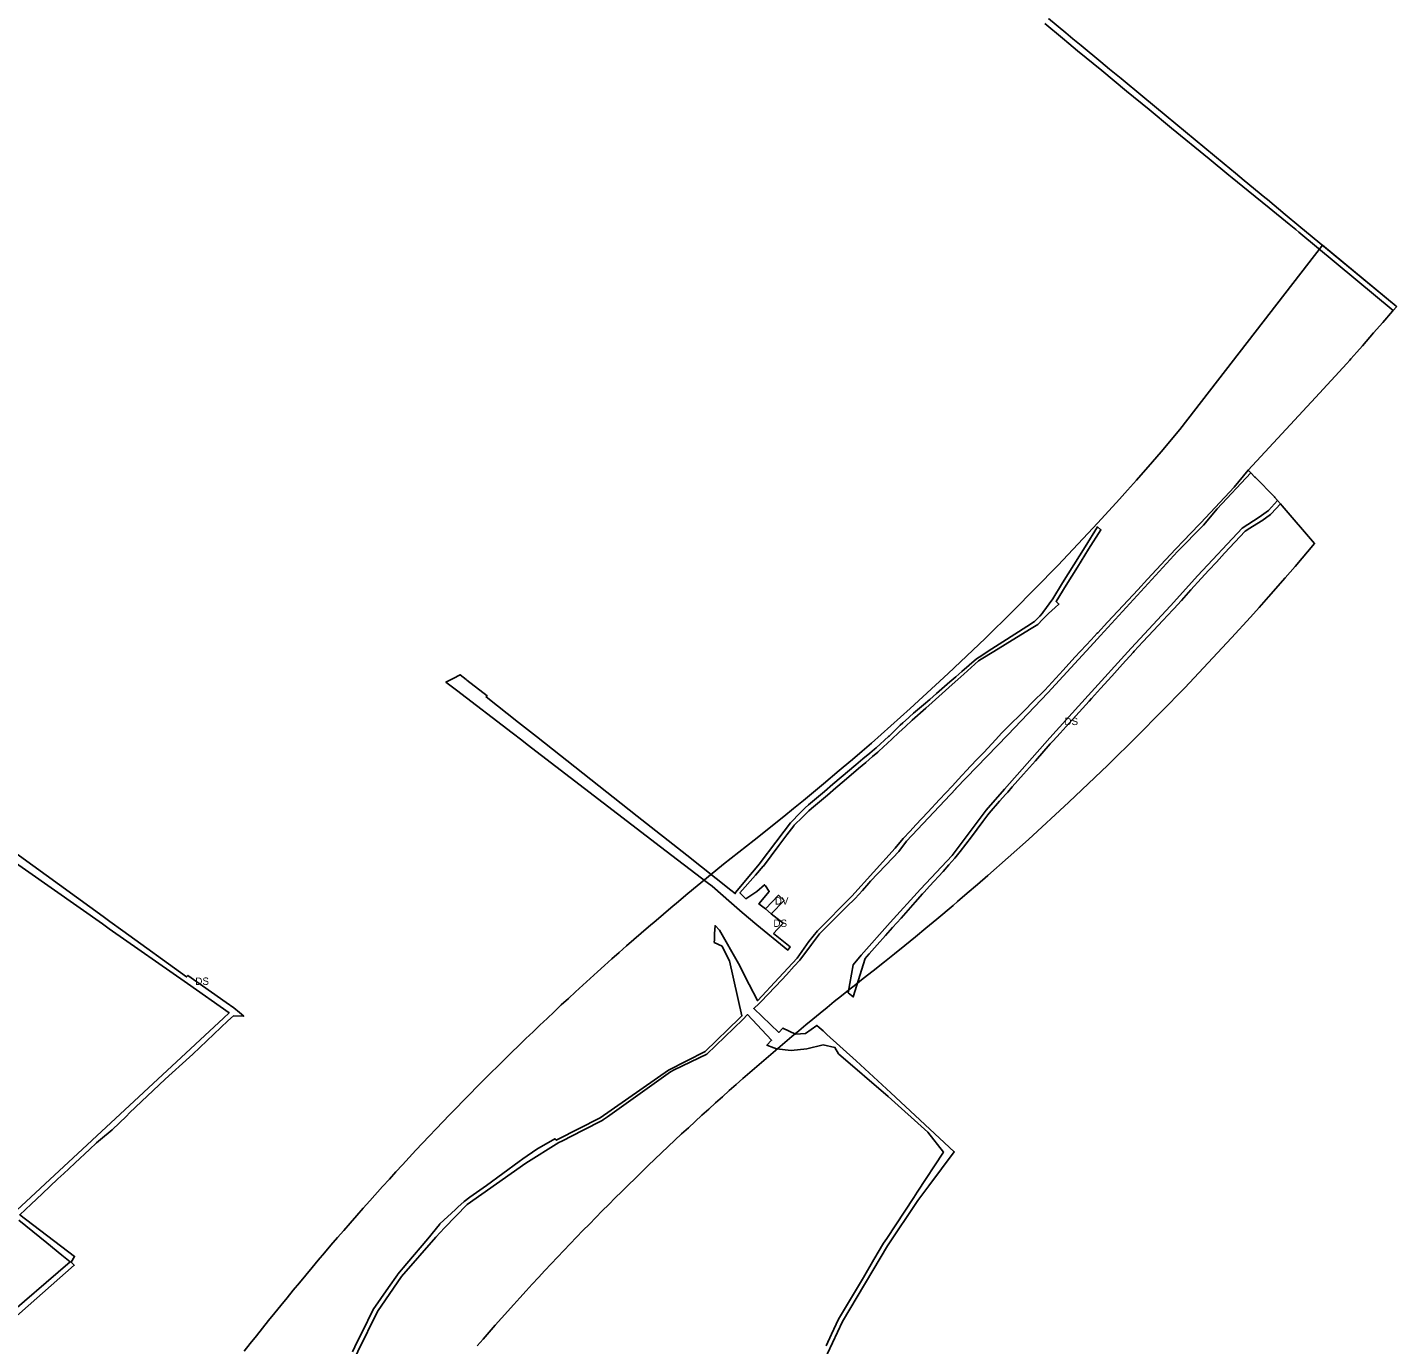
# Model space of a CAD drawing. Extents: x -537034 to -534353, y -1176562 to -1173176.
# Drawn here: x -535284 to -534353, y -1175321 to -1174424 of the extents above; entities that cross this region are included whole.
import ezdxf

# ---------------------------------------------------------------- set-up
doc = ezdxf.new("R2010")
doc.units = 0
for name, color, linetype in [('90320013', 7, 'Continuous'), ('90350013', 7, 'Continuous'), ('90350033', 7, 'Continuous')]:
    doc.layers.add(name, color=color, linetype=linetype)

msp = doc.modelspace()

# ---------------------------------------------------------------- linework, layer by layer
at = {"layer": '90320013'}
for points in [[(-534589.93, -1174418.12), (-534578.03, -1174428.04), (-534573.25, -1174432.03), (-534567.68, -1174436.64), (-534554.19, -1174447.79), (-534548.35, -1174452.63), (-534540.48, -1174459.14), (-534525.72, -1174471.35), (-534509.87, -1174484.46), (-534483.54, -1174506.24), (-534470.29, -1174517.2), (-534462.6, -1174523.56), (-534456.81, -1174528.36), (-534442.82, -1174539.95), (-534440.99, -1174541.47), (-534428.86, -1174551.52), (-534419.54, -1174559.24), (-534353.44, -1174614.02), (-534353.08, -1174614.32), (-534355.38, -1174616.95), (-534419.61, -1174563.52), (-534421.64, -1174561.87), (-534426.11, -1174558.23), (-534439.81, -1174547.07), (-534454.04, -1174535.48), (-534464.98, -1174526.57), (-534467.19, -1174524.75), (-534480.58, -1174513.75), (-534506.13, -1174492.75), (-534521.39, -1174480.21), (-534536.75, -1174467.59), (-534553.67, -1174453.68), (-534570.13, -1174440.15), (-534576.11, -1174435.24), (-534580.43, -1174431.59), (-534592.27, -1174421.58)], [(-535063.39, -1175325.47), (-535060.09, -1175318.76), (-535056.8, -1175312.07), (-535049.22, -1175296.61), (-535038.82, -1175281.72), (-535032.81, -1175273.11), (-535032.45, -1175272.59), (-535026.36, -1175265.47), (-535012.03, -1175248.73), (-535004.26, -1175238.84), (-535003.94, -1175238.43), (-534993.31, -1175228.6), (-534991.63, -1175227.05), (-534987.36, -1175223.18), (-534983.42, -1175220.32), (-534972.25, -1175212.22), (-534949.86, -1175195.98), (-534947.44, -1175194.22), (-534937.89, -1175187.69), (-534925.65, -1175180.5), (-534924.68, -1175181.38), (-534923.98, -1175180.93), (-534894.94, -1175166.32), (-534848.38, -1175133.87), (-534823.52, -1175121.25), (-534800, -1175098.5), (-534798.45, -1175096.97), (-534806.93, -1175059.47), (-534810.08, -1175053.22), (-534811.97, -1175049.46), (-534817.23, -1175046.88), (-534817.15, -1175045), (-534816.98, -1175041.13), (-534816.74, -1175035.44), (-534813.71, -1175038.69), (-534800.74, -1175061.15), (-534793.42, -1175075.61), (-534787.86, -1175086.44), (-534787.72, -1175086.34), (-534773.26, -1175070.93), (-534773.24, -1175070.91), (-534760.89, -1175057.67), (-534760.8, -1175057.54), (-534752.93, -1175046.38), (-534747.13, -1175039.14), (-534723.62, -1175015.5), (-534694.19, -1174982.86), (-534688.65, -1174976.17), (-534684.1, -1174971.29), (-534680.11, -1174967.01), (-534676.03, -1174962.63), (-534672.06, -1174958.37), (-534663.93, -1174949.64), (-534659.79, -1174945.2), (-534655.44, -1174940.54), (-534655.2, -1174940.28), (-534651.23, -1174936.04), (-534642.84, -1174927.08), (-534638.3, -1174922.23), (-534633.94, -1174917.57), (-534625.7, -1174908.76), (-534621.84, -1174904.63), (-534620.16, -1174902.84), (-534618.12, -1174900.81), (-534606.77, -1174889.47), (-534599.87, -1174882.57), (-534593.35, -1174876.06), (-534592.47, -1174875.18), (-534579.89, -1174861.57), (-534571.86, -1174852.88), (-534564.27, -1174844.66), (-534560.85, -1174840.96), (-534556.76, -1174836.54), (-534556.43, -1174836.18), (-534549.73, -1174828.99), (-534542.79, -1174821.53), (-534535.79, -1174814.01), (-534529.2, -1174806.94), (-534522.47, -1174799.71), (-534516.46, -1174793.26), (-534510.2, -1174786.54), (-534503.37, -1174779.2), (-534498.14, -1174773.7), (-534493.01, -1174768.32), (-534487.23, -1174762.24), (-534486.32, -1174761.29), (-534463.51, -1174737.19), (-534454.07, -1174725.53), (-534452.32, -1174727.32), (-534475.1, -1174751.76), (-534484.54, -1174763.09), (-534502.13, -1174780.9), (-534554.55, -1174837.98), (-534559.14, -1174842.98), (-534590.44, -1174877.09), (-534617.54, -1174905.69), (-534652.92, -1174942.24), (-534653.01, -1174942.33), (-534686.41, -1174978.09), (-534691.73, -1174984.99), (-534695.79, -1174989.31), (-534700.74, -1174994.57), (-534710.89, -1175005.34), (-534712.15, -1175006.68), (-534716.5, -1175011.48), (-534721.5, -1175016.99), (-534727.33, -1175022.8), (-534733.34, -1175028.8), (-534745.39, -1175040.83), (-534745.62, -1175041.13), (-534751.09, -1175048.36), (-534759.09, -1175058.95), (-534762.82, -1175063.03), (-534768.18, -1175068.9), (-534771.39, -1175072.42), (-534785.44, -1175087.07), (-534786.8, -1175088.49), (-534790.32, -1175091.91), (-534790.4, -1175091.99), (-534773.31, -1175108.17), (-534770.56, -1175105.2), (-534761.9, -1175109.38), (-534755.11, -1175109), (-534747.48, -1175103.4), (-534745.98, -1175104.75), (-534743.28, -1175107.18), (-534740.58, -1175109.61), (-534720.8, -1175127.43), (-534697.1, -1175149.18), (-534653.97, -1175189.37), (-534671.31, -1175212.56), (-534678.69, -1175222.42), (-534699.3, -1175253.32), (-534730.05, -1175304.93), (-534747.12, -1175341.05)], [(-535310.83, -1174973.08), (-535242.13, -1175022.75), (-535233.05, -1175029.31), (-535228.44, -1175032.64), (-535219.53, -1175039.08), (-535176.19, -1175070.42), (-535175.34, -1175069.39), (-535149.3, -1175087.74), (-535144.09, -1175091.41), (-535140.17, -1175094.69), (-535137.28, -1175097.12), (-535144.39, -1175096.9), (-535148.04, -1175100.34), (-535171.9, -1175122.87), (-535174.24, -1175125.08), (-535190.77, -1175139.87), (-535215.05, -1175162.99), (-535217.18, -1175165.05), (-535226.88, -1175174.43), (-535234.65, -1175180.94), (-535237.5, -1175183.32), (-535242.22, -1175187.74), (-535252.09, -1175196.99), (-535256.36, -1175200.99), (-535259.81, -1175204.23), (-535263.71, -1175207.89), (-535274.41, -1175217.92), (-535281.94, -1175224.98), (-535289.65, -1175232.2), (-535252.39, -1175260.55), (-535254.7, -1175264.4), (-535252.65, -1175266.55), (-535299.55, -1175307.94)], [(-535294.94, -1175232.04), (-535151.14, -1175098.4), (-535147.24, -1175094.77), (-535175.51, -1175074.96), (-535228.85, -1175037.59), (-535233.44, -1175034.37), (-535301.06, -1174986.97)], [(-534741.19, -1175321.42), (-534737.42, -1175313.42), (-534734.3, -1175306.78), (-534732.7, -1175303.37), (-534730.67, -1175299.94), (-534723.88, -1175288.45), (-534715.83, -1175274.83), (-534708.7, -1175262.76), (-534702.15, -1175251.67), (-534699.91, -1175248.4), (-534681.52, -1175220.48), (-534679.16, -1175216.88), (-534661.36, -1175189.66), (-534671.99, -1175175.95), (-534698.96, -1175151.8), (-534732.83, -1175122.62), (-534735.14, -1175118.41), (-534743.23, -1175116.69), (-534754.23, -1175119.31), (-534764.86, -1175120.57), (-534774.86, -1175119.44), (-534776.64, -1175118.75), (-534781.42, -1175116.91), (-534778.21, -1175113.45), (-534778.22, -1175113.45), (-534794.55, -1175096.02), (-534797.92, -1175099.3), (-534822.38, -1175122.93), (-534844.45, -1175133.62), (-534847.04, -1175134.87), (-534889.89, -1175165.51), (-534892.59, -1175167.44), (-534893.48, -1175168.07), (-534906.46, -1175174.67), (-534921.01, -1175182.07), (-534922.88, -1175183.02), (-534945.43, -1175197.06), (-534985.25, -1175225.31), (-535000.77, -1175241.14), (-535006.62, -1175247.42), (-535030.1, -1175274.28), (-535046.44, -1175297.98), (-535073.18, -1175352.43)], [(-535302.84, -1175305.19), (-535255.37, -1175264.33), (-535261.08, -1175259.67), (-535271.33, -1175251.31), (-535290.22, -1175235.89)]]:
    msp.add_lwpolyline(points, dxfattribs=at)
for points in [[(-534726.06, -1175081.25), (-534722.76, -1175062.11), (-534717.3, -1175055.5), (-534697.52, -1175033.38), (-534676.86, -1175010.7), (-534655.43, -1174987.67), (-534632.39, -1174956.93), (-534619.84, -1174942.57), (-534589.01, -1174907.71), (-534562.86, -1174878.98), (-534533.72, -1174846.67), (-534506.9, -1174817.91), (-534488.33, -1174797.34), (-534458.12, -1174764.98), (-534446.52, -1174757.52), (-534440.14, -1174752.91), (-534434.05, -1174746.09), (-534432.09, -1174748.37), (-534438.37, -1174755.36), (-534438.8, -1174755.67), (-534444.75, -1174759.97), (-534445.17, -1174760.23), (-534452.95, -1174765.07), (-534456.21, -1174767.1), (-534470.07, -1174782.05), (-534475.68, -1174788.11), (-534480.75, -1174793.58), (-534486.14, -1174799.39), (-534492.97, -1174806.95), (-534499.52, -1174814.21), (-534504.67, -1174819.92), (-534505.32, -1174820.62), (-534512.17, -1174827.96), (-534518.45, -1174834.69), (-534525.62, -1174842.38), (-534531.53, -1174848.72), (-534532.32, -1174849.59), (-534539.53, -1174857.59), (-534546.87, -1174865.73), (-534554.5, -1174874.18), (-534560.64, -1174880.98), (-534562.26, -1174882.76), (-534575.89, -1174897.74), (-534581.98, -1174904.44), (-534586.79, -1174909.73), (-534588.66, -1174911.85), (-534598.76, -1174923.27), (-534602.87, -1174927.92), (-534606.8, -1174932.37), (-534614.56, -1174941.14), (-534617.59, -1174944.56), (-534618.91, -1174946.08), (-534623.14, -1174950.91), (-534630.19, -1174958.97), (-534631.12, -1174960.2), (-534634.53, -1174964.69), (-534638.47, -1174969.88), (-534642.34, -1174974.97), (-534649.98, -1174985.02), (-534653.5, -1174989.66), (-534657.59, -1174994.15), (-534661.59, -1174998.56), (-534670.85, -1175008.75), (-534674.52, -1175012.78), (-534675.58, -1175013.96), (-534680.57, -1175019.56), (-534690.19, -1175030.35), (-534695.91, -1175036.77), (-534700.74, -1175042.19), (-534706.46, -1175048.6), (-534711.9, -1175054.7), (-534713.41, -1175056.39), (-534714.69, -1175057.83), (-534722.75, -1175084.04), (-534725.07, -1175082.09)], [(-534782.29, -1175024), (-534778.49, -1175027.49), (-534770.39, -1175033.81), (-534774.24, -1175037.93), (-534776.91, -1175040.75), (-534765.58, -1175050.02), (-534767.31, -1175052.15), (-534788.2, -1175034.87), (-534798.18, -1175026.62), (-534805.63, -1175020.1), (-534818.78, -1175008.59), (-534821.98, -1175006.14), (-534853.75, -1174981.84), (-534944.54, -1174912.26), (-534948.24, -1174909.32), (-534954.69, -1174904.38), (-534992.69, -1174875.28), (-534999.77, -1174869.82), (-534994.52, -1174867.04), (-534990.63, -1174864.98), (-534990.18, -1174864.74), (-534985.93, -1174868.07), (-534985.56, -1174868.36), (-534971.8, -1174879.12), (-534972.43, -1174879.91), (-534950.35, -1174897.34), (-534938.24, -1174906.9), (-534869.76, -1174960.94), (-534836.01, -1174987.56), (-534805.96, -1175011.28), (-534802.96, -1175013.64), (-534802.78, -1175012.88), (-534791.25, -1174999.12), (-534786.4, -1174993.33), (-534785.92, -1174992.69), (-534775.34, -1174978.66), (-534769.74, -1174971.23), (-534765.49, -1174965.6), (-534764.81, -1174964.9), (-534759.21, -1174959.17), (-534755.41, -1174955.28), (-534753.14, -1174953.36), (-534742.3, -1174944.19), (-534736.54, -1174939.32), (-534730.87, -1174934.52), (-534721.01, -1174926.18), (-534716.11, -1174922.04), (-534711.49, -1174918.14), (-534708.32, -1174915.45), (-534707.2, -1174914.47), (-534698.64, -1174906.9), (-534698.23, -1174906.49), (-534693.48, -1174901.76), (-534690.89, -1174899.19), (-534688.97, -1174897.47), (-534685.1, -1174894.02), (-534684.36, -1174893.38), (-534681.63, -1174891.01), (-534674.99, -1174885.26), (-534670.72, -1174881.56), (-534666.1, -1174877.56), (-534656.99, -1174869.67), (-534652.89, -1174866.12), (-534648.87, -1174862.64), (-534638.95, -1174854.04), (-534636.95, -1174852.75), (-534628.44, -1174847.25), (-534620.87, -1174842.36), (-534604.65, -1174831.87), (-534599.49, -1174828.54), (-534595.88, -1174824.89), (-534594.13, -1174823.13), (-534593.65, -1174822.45), (-534587.03, -1174813.03), (-534580.26, -1174802.17), (-534572.63, -1174789.92), (-534565.02, -1174777.71), (-534556.56, -1174764.15), (-534554.28, -1174766.1), (-534562.58, -1174779.41), (-534570.19, -1174791.62), (-534577.84, -1174803.89), (-534584.75, -1174814.98), (-534582.77, -1174816.67), (-534585.4, -1174819.11), (-534589.81, -1174823.19), (-534591.85, -1174825.08), (-534593.92, -1174827.17), (-534597.21, -1174830.49), (-534602.88, -1174833.99), (-534619.38, -1174844.19), (-534627.07, -1174848.94), (-534635.7, -1174854.27), (-534637.43, -1174855.34), (-534647.49, -1174864.35), (-534651.46, -1174867.9), (-534655.51, -1174871.52), (-534664.5, -1174879.56), (-534669.06, -1174883.64), (-534673.31, -1174887.44), (-534682.55, -1174895.71), (-534682.82, -1174895.96), (-534687.06, -1174899.88), (-534691.61, -1174904.08), (-534696.53, -1174908.62), (-534705.36, -1174916.77), (-534706.04, -1174917.4), (-534709.63, -1174920.47), (-534714.23, -1174924.39), (-534719.08, -1174928.54), (-534728.92, -1174936.95), (-534734.55, -1174941.76), (-534740.27, -1174946.65), (-534751.08, -1174955.89), (-534752.89, -1174957.43), (-534757.18, -1174961.64), (-534762.89, -1174967.22), (-534763.21, -1174967.54), (-534767.78, -1174973.61), (-534773.36, -1174981.02), (-534783.84, -1174994.93), (-534784, -1174995.14), (-534789.27, -1175001.16), (-534799.77, -1175013.15), (-534795.76, -1175017.23), (-534788.3, -1175012.3), (-534782.97, -1175007.65), (-534782.3, -1175008.34), (-534779.83, -1175012.16), (-534786.84, -1175020.73)]]:
    msp.add_lwpolyline(points, close=True, dxfattribs=at)
at = {"layer": '90350013'}
msp.add_lwpolyline([(-534782.29, -1175024), (-534773.59, -1175014.79), (-534769.81, -1175018.3), (-534778.49, -1175027.49)], close=True, dxfattribs=at)
at = {"layer": '90350033'}
msp.add_lwpolyline([(-535136.94, -1175325.16), (-535132.84, -1175319.92), (-535128.73, -1175314.69), (-535124.59, -1175309.47), (-535120.44, -1175304.27), (-535116.27, -1175299.08), (-535112.08, -1175293.9), (-535107.88, -1175288.74), (-535103.66, -1175283.58), (-535099.42, -1175278.45), (-535095.16, -1175273.32), (-535090.89, -1175268.21), (-535086.6, -1175263.12), (-535082.42, -1175258.19), (-535077.98, -1175252.95), (-535073.49, -1175247.76), (-535069.26, -1175242.87), (-535064.89, -1175237.85), (-535060.49, -1175232.83), (-535056.09, -1175227.84), (-535051.6, -1175222.78), (-535042.82, -1175213), (-535038.28, -1175207.99), (-535033.79, -1175203.07), (-535029.28, -1175198.16), (-535024.76, -1175193.26), (-535020.22, -1175188.38), (-535015.66, -1175183.52), (-535011.09, -1175178.67), (-535006.5, -1175173.83), (-535001.9, -1175169.01), (-534997.28, -1175164.21), (-534992.65, -1175159.42), (-534988, -1175154.65), (-534983.33, -1175149.89), (-534978.65, -1175145.15), (-534973.95, -1175140.42), (-534969.24, -1175135.71), (-534964.51, -1175131.02), (-534959.77, -1175126.34), (-534955.02, -1175121.68), (-534950.39, -1175117.18), (-534945.47, -1175112.38), (-534940.5, -1175107.65), (-534935.84, -1175103.19), (-534931.01, -1175098.61), (-534926.16, -1175094.05), (-534921.3, -1175089.5), (-534916.43, -1175084.97), (-534911.54, -1175080.46), (-534906.64, -1175075.96), (-534901.72, -1175071.48), (-534896.79, -1175067.02), (-534891.85, -1175062.57), (-534886.89, -1175058.14), (-534881.92, -1175053.73), (-534876.93, -1175049.33), (-534871.93, -1175044.95), (-534866.92, -1175040.59), (-534861.89, -1175036.25), (-534856.85, -1175031.92), (-534851.8, -1175027.61), (-534846.74, -1175023.32), (-534841.66, -1175019.04), (-534836.56, -1175014.79), (-534831.46, -1175010.55), (-534826.34, -1175006.33), (-534821.21, -1175002.13), (-534816.07, -1174997.94), (-534810.91, -1174993.77), (-534805.75, -1174989.62), (-534800.57, -1174985.49), (-534795.38, -1174981.38), (-534790.18, -1174977.29), (-534783.54, -1174972.06), (-534776.41, -1174966.39), (-534769.98, -1174961.23), (-534763.24, -1174955.78), (-534756.51, -1174950.28), (-534749.82, -1174944.77), (-534742.88, -1174939), (-534732.18, -1174929.99), (-534729.52, -1174927.75), (-534723.23, -1174922.37), (-534716.63, -1174916.68), (-534710.36, -1174911.24), (-534684.02, -1174887.83), (-534658.03, -1174863.91), (-534632.98, -1174840.01), (-534614.26, -1174821.59), (-534583.65, -1174790.4), (-534559.44, -1174764.73), (-534553.86, -1174758.68), (-534541.6, -1174745.2), (-534536.13, -1174739.11), (-534530.09, -1174732.33), (-534519.24, -1174719.98), (-534513.25, -1174713.07), (-534500.44, -1174697.95), (-534403.55, -1174572.5), (-534353.44, -1174614.02), (-534353.08, -1174614.32), (-534355.38, -1174616.95), (-534355.78, -1174617.4), (-534362.47, -1174625.07), (-534368.7, -1174632.2), (-534376.27, -1174640.88), (-534380.19, -1174645.37), (-534384.14, -1174649.9), (-534384.9, -1174650.72), (-534387.03, -1174653.03), (-534408.37, -1174676.1), (-534454.07, -1174725.53), (-534452.32, -1174727.32), (-534449.49, -1174730.22), (-534449.18, -1174730.55), (-534436.26, -1174743.82), (-534435.92, -1174744.17), (-534434.05, -1174746.09), (-534432.09, -1174748.37), (-534430.84, -1174749.83), (-534408.87, -1174775.5), (-534422.13, -1174791.15), (-534428.84, -1174798.89), (-534440.2, -1174811.82), (-534446.66, -1174819.09), (-534452.58, -1174825.67), (-534465.38, -1174839.74), (-534471.68, -1174846.57), (-534497.16, -1174873.59), (-534529.34, -1174906.39), (-534549.48, -1174926.2), (-534575.97, -1174951.47), (-534603.52, -1174976.83), (-534631.15, -1175001.39), (-534638.12, -1175007.44), (-534645.11, -1175013.46), (-534651.79, -1175019.16), (-534654.77, -1175021.69), (-534665.88, -1175031.04), (-534673.31, -1175037.22), (-534680.41, -1175043.07), (-534687.55, -1175048.9), (-534694.69, -1175054.68), (-534701.53, -1175060.16), (-534709.07, -1175066.16), (-534715.94, -1175071.57), (-534721.01, -1175075.56), (-534725.89, -1175079.43), (-534730.76, -1175083.31), (-534735.62, -1175087.21), (-534740.48, -1175091.14), (-534745.32, -1175095.08), (-534750.14, -1175099.03), (-534754.95, -1175102.99), (-534759.75, -1175106.98), (-534764.54, -1175110.99), (-534769.32, -1175115.01), (-534774.08, -1175119.04), (-534778.83, -1175123.1), (-534783.57, -1175127.16), (-534788.3, -1175131.25), (-534793.02, -1175135.36), (-534797.72, -1175139.47), (-534802.41, -1175143.61), (-534807.08, -1175147.76), (-534811.75, -1175151.92), (-534816.4, -1175156.11), (-534821.04, -1175160.31), (-534825.66, -1175164.52), (-534830.28, -1175168.75), (-534834.87, -1175173), (-534839.45, -1175177.25), (-534844.02, -1175181.53), (-534848.58, -1175185.83), (-534853.13, -1175190.14), (-534857.66, -1175194.46), (-534862.19, -1175198.78), (-534866.67, -1175203.15), (-534871.16, -1175207.52), (-534875.64, -1175211.91), (-534880.1, -1175216.31), (-534884.55, -1175220.73), (-534888.98, -1175225.15), (-534893.4, -1175229.6), (-534897.8, -1175234.06), (-534902.19, -1175238.53), (-534906.56, -1175243.02), (-534910.92, -1175247.53), (-534915.26, -1175252.04), (-534919.6, -1175256.58), (-534923.91, -1175261.13), (-534928.21, -1175265.68), (-534932.5, -1175270.27), (-534936.77, -1175274.85), (-534941.02, -1175279.46), (-534945.26, -1175284.08), (-534949.49, -1175288.71), (-534953.7, -1175293.35), (-534962.07, -1175302.69), (-534966.23, -1175307.37), (-534970.38, -1175312.07), (-534974.51, -1175316.79), (-534978.62, -1175321.51)], dxfattribs=at)

# ---------------------------------------------------------------- texts
at = {"layer": '90320013'}
for rotation, p in [(0, (-534579.07, -1174899.02)), (360, (-534777.03, -1175036.37)), (0, (-535170.28, -1175075.8))]:
    msp.add_text('DS', height=5, rotation=rotation, dxfattribs=at).set_placement(p)
at = {"layer": '90350013'}
msp.add_text('DV', height=5, rotation=0, dxfattribs=at).set_placement((-534776.05, -1175021.15))

doc.saveas('drawing.dxf')
